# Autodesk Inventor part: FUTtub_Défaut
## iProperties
Shininess: 64.0
Length Units: 11269
Angle Units: 11279
Time Units: 11290
Mass Units: 11283
Length Display Precision: 3
Angle Display Precision: 2
Compacted: True
Part Number: FUTtub_Défaut
Document SubType Name: Modeling
Created: 2006-11
Material: Par défaut
Designer: profs_sti
Density: 0.0
Volumn: 0.0
Area: 0.0
PropertySet Name: Model Information
Control State: 0
Master: False
Checked Out: False
Author: profs_sti
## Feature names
1. Base1
